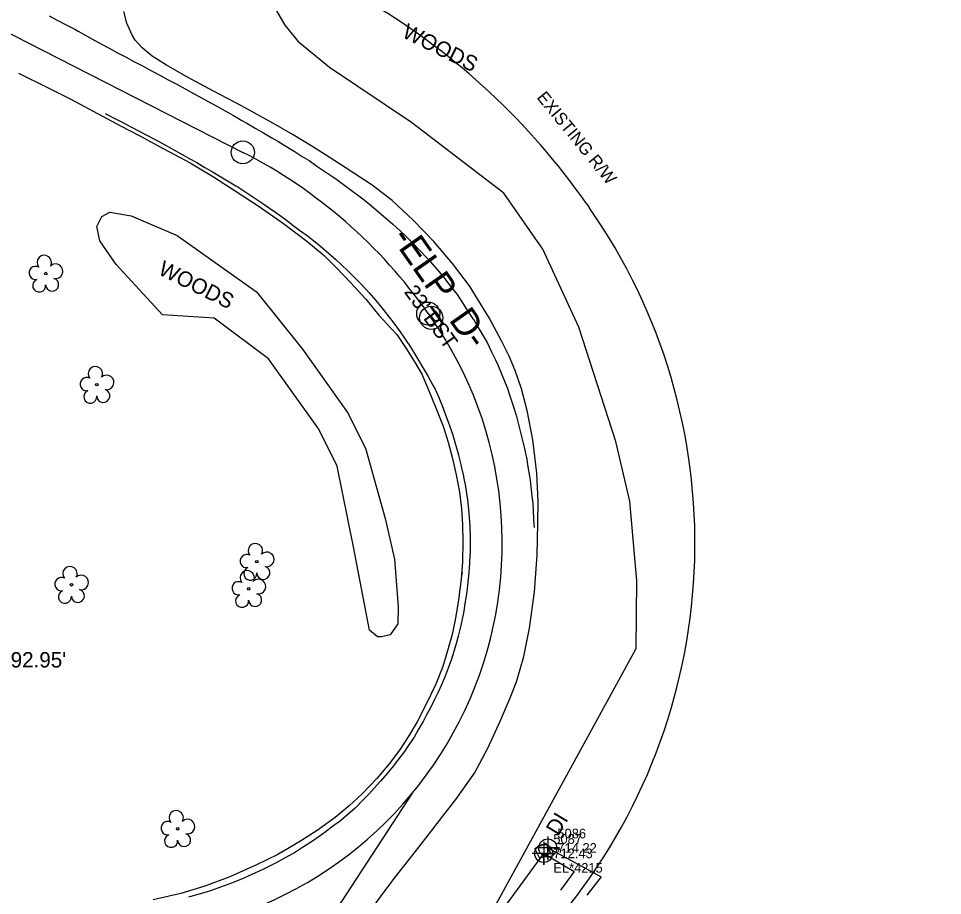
# Model space of a CAD drawing. Extents: x 1516784 to 1522736, y 634838 to 639369.
# Drawn here: x 1520674.9 to 1520914.7, y 637790.3 to 638018 of the extents above; entities that cross this region are included whole.
import ezdxf

# ---------------------------------------------------------------- set-up
doc = ezdxf.new("R2010")
doc.units = 0
for name, color, linetype in [('COGO Default Point Elevation', 7, 'Continuous'), ('COGO Default Point Number', 7, 'Continuous'), ('Exist Environmental Wetland Boundary Text', 7, 'Continuous'), ('Exist Horizontal Alignment Direction Label', 7, 'Continuous'), ('Exist Horizontal Alignment Point', 7, 'Continuous'), ('Exist Right of Way Line', 7, 'Continuous'), ('Exist Right of Way Line Text', 7, 'Continuous'), ('Exist Roads EOP Text', 7, 'Continuous'), ('Exist Structure Minor Drop Inlet', 7, 'Continuous'), ('Exist Structure Minor Drop Inlet Cogo Elevation', 7, 'Continuous'), ('Exist Structure Minor Drop Inlet Cogo Number', 7, 'Continuous'), ('Exist Structure Minor Drop Inlet Cogo Point CELL', 7, 'Continuous'), ('Exist Structure Minor Drop Inlet Leader', 7, 'Continuous'), ('Exist Structure Minor Drop Inlet Text', 7, 'Continuous'), ('Exist Structure Minor Pipes RCP 15 Inch', 7, 'Continuous'), ('Exist Structure Minor Pipes RCP 15 Inch Cogo Comment', 7, 'Continuous'), ('Exist Structure Minor Pipes RCP 15 Inch Cogo Elevation', 7, 'Continuous'), ('Exist Structure Minor Pipes RCP 15 Inch Cogo Number', 7, 'Continuous'), ('Exist Structure Minor Pipes RCP 15 Inch Cogo Point CELL', 7, 'Continuous'), ('Exist Structure Minor Pipes RCP 15 Inch Leader', 7, 'Continuous'), ('Exist Structure Minor Pipes RCP 66 Inch Invert', 7, 'Continuous'), ('Exist Vegetation Tree CELL', 7, 'Continuous'), ('Exist Vegetation Woods Line', 7, 'Continuous'), ('Exist Vegetation Woods Line Text', 7, 'Continuous'), ('Scratch_Level_5', 7, 'Continuous')]:
    doc.layers.add(name, color=color, linetype=linetype)

msp = doc.modelspace()

# ---------------------------------------------------------------- linework, layer by layer
at = {"layer": 'COGO Default Point Elevation'}
for points in [[(1520682.82, 638018.69), (1520685.04, 638017.54), (1520687.25, 638016.38), (1520689.46, 638015.22), (1520690.35, 638014.76), (1520692.53, 638013.54), (1520694.71, 638012.33), (1520696.89, 638011.11), (1520698.37, 638010.28), (1520700.58, 638009.12), (1520702.79, 638007.95), (1520705, 638006.78), (1520707.21, 638005.62), (1520709.42, 638004.45), (1520711.54, 638003.33), (1520713.73, 638002.14), (1520715.93, 638000.94), (1520718.12, 637999.75), (1520720.32, 637998.55), (1520722.51, 637997.36), (1520724.13, 637996.47), (1520726.31, 637995.25), (1520728.49, 637994.03), (1520730.66, 637992.8), (1520732.84, 637991.58), (1520734.16, 637990.84), (1520736.32, 637989.58), (1520738.48, 637988.32), (1520740.63, 637987.06), (1520742.13, 637986.19), (1520744.25, 637984.87), (1520746.37, 637983.55), (1520748.49, 637982.23), (1520750.26, 637981.13), (1520752.33, 637979.73), (1520754.4, 637978.33), (1520756.47, 637976.94), (1520757.17, 637976.46), (1520759.18, 637974.97), (1520761.18, 637973.48), (1520763.19, 637971.99), (1520764.54, 637970.98), (1520766.45, 637969.38), (1520768.37, 637967.78), (1520770.12, 637966.31), (1520771.97, 637964.63), (1520773.82, 637962.96), (1520775.56, 637961.38), (1520777.3, 637959.58), (1520779.03, 637957.78), (1520780.76, 637955.98), (1520781.17, 637955.56), (1520782.8, 637953.66), (1520784.43, 637951.77), (1520784.87, 637951.26), (1520786.39, 637949.28), (1520787.92, 637947.31), (1520788.67, 637946.33), (1520790.05, 637944.25), (1520791.43, 637942.17), (1520792.81, 637940.09), (1520792.91, 637939.94), (1520794.18, 637937.79), (1520795.45, 637935.64), (1520796.46, 637933.92), (1520797.55, 637931.67), (1520798.64, 637929.42), (1520799.29, 637928.1), (1520800.24, 637925.79), (1520801.2, 637923.48), (1520801.72, 637922.22), (1520802.48, 637919.84), (1520803.23, 637917.46), (1520803.99, 637915.06), (1520804.62, 637912.64), (1520805.25, 637910.22), (1520805.52, 637909.18), (1520806.07, 637906.74), (1520806.63, 637904.31), (1520806.67, 637904.11), (1520807.08, 637901.65), (1520807.49, 637899.19), (1520807.66, 637898.16), (1520807.94, 637895.68), (1520808.21, 637893.2), (1520808.23, 637892.97), (1520808.39, 637890.47), (1520808.54, 637887.98), (1520808.68, 637885.85)], [(1520697.33, 637993.37), (1520699.55, 637992.22), (1520701.77, 637991.07), (1520703.99, 637989.93), (1520706.21, 637988.78), (1520707.99, 637987.86), (1520710.19, 637986.67), (1520712.38, 637985.48), (1520714.58, 637984.29), (1520715.18, 637983.96), (1520717.36, 637982.74), (1520719.54, 637981.52), (1520721.11, 637980.64), (1520723.26, 637979.36), (1520725.41, 637978.09), (1520726.97, 637977.16), (1520729.12, 637975.88), (1520731.26, 637974.59), (1520731.76, 637974.29), (1520733.85, 637972.92), (1520735.94, 637971.55), (1520736.48, 637971.19), (1520738.55, 637969.79), (1520740.61, 637968.39), (1520741.08, 637968.07), (1520743.09, 637966.59), (1520745.11, 637965.11), (1520745.82, 637964.58), (1520747.83, 637963.1), (1520749.83, 637961.62), (1520750.32, 637961.26), (1520752.27, 637959.7), (1520752.69, 637959.37), (1520754.59, 637957.74), (1520755.31, 637957.12), (1520757.18, 637955.45), (1520758.58, 637954.2), (1520760.38, 637952.47), (1520761.19, 637951.69), (1520762.95, 637949.92), (1520763.49, 637949.38), (1520765.19, 637947.55), (1520765.91, 637946.78), (1520767.56, 637944.84), (1520769.16, 637942.93), (1520769.53, 637942.49), (1520771.05, 637940.52), (1520771.98, 637939.3), (1520773.45, 637937.28), (1520774.49, 637935.84), (1520775.91, 637933.78), (1520776.05, 637933.58), (1520777.38, 637931.47), (1520777.47, 637931.33), (1520778.76, 637929.19), (1520779.39, 637928.14), (1520780.67, 637925.99), (1520781.21, 637925.06), (1520782.4, 637922.86), (1520783, 637921.76), (1520784, 637919.47), (1520784.12, 637919.19), (1520785.05, 637916.87), (1520785.37, 637916.08), (1520786.24, 637913.73), (1520786.41, 637913.28), (1520787.22, 637910.92), (1520787.59, 637909.85), (1520788.3, 637907.46), (1520788.38, 637907.19), (1520789.03, 637904.78), (1520789.07, 637904.64), (1520789.65, 637902.21), (1520789.77, 637901.68), (1520790.31, 637899.24), (1520790.35, 637899.04), (1520790.83, 637896.54), (1520791.21, 637894.07), (1520791.35, 637893.13), (1520791.61, 637890.6), (1520791.81, 637888.59), (1520791.97, 637886.03), (1520792.05, 637883.53), (1520792.06, 637883.12), (1520792.05, 637880.62), (1520792.04, 637879.58), (1520791.92, 637877.09), (1520791.9, 637876.65), (1520791.7, 637874.16), (1520791.58, 637872.56), (1520791.29, 637870.08), (1520791.12, 637868.6), (1520790.72, 637866.14), (1520790.4, 637864.14), (1520789.89, 637861.69), (1520789.56, 637860.09), (1520788.97, 637857.67), (1520788.57, 637856.07), (1520787.83, 637853.69), (1520787.2, 637851.69), (1520786.34, 637849.34), (1520785.6, 637847.31), (1520784.62, 637845.02), (1520783.88, 637843.28), (1520782.78, 637841.04), (1520781.9, 637839.26), (1520780.7, 637837.07), (1520779.84, 637835.51), (1520778.61, 637833.33), (1520777.55, 637831.48), (1520776.13, 637829.42), (1520775, 637827.77), (1520773.5, 637825.77), (1520772.14, 637823.95), (1520770.52, 637822.04), (1520768.85, 637820.07), (1520767.17, 637818.21), (1520765.86, 637816.76), (1520764.11, 637814.97), (1520762.37, 637813.18), (1520762.2, 637813.01), (1520760.31, 637811.38), (1520758.39, 637809.72), (1520756.39, 637808.23), (1520754.39, 637806.73), (1520754.11, 637806.52), (1520752.05, 637805.1), (1520750.67, 637804.15), (1520748.57, 637802.81), (1520746.46, 637801.46), (1520746.12, 637801.24), (1520743.92, 637800.05), (1520741.73, 637798.86), (1520740.66, 637798.29), (1520738.41, 637797.2), (1520736.16, 637796.12), (1520735.61, 637795.85), (1520733.31, 637794.86), (1520731.02, 637793.87), (1520730.8, 637793.78), (1520728.46, 637792.92), (1520727.05, 637792.4), (1520724.69, 637791.6), (1520723.61, 637791.23), (1520721.43, 637790.57), (1520719.02, 637789.88)]]:
    msp.add_lwpolyline(points, dxfattribs=at)
at = {"layer": 'COGO Default Point Number'}
msp.add_line((1520789.86, 637872.85), (1520790.06, 637874.32), dxfattribs=at)
for points in [[(1520766.29, 637786.51), (1520769.49, 637790.94), (1520772.99, 637795.51), (1520776.91, 637800.55), (1520781.16, 637805.97), (1520785.03, 637810.93), (1520788.36, 637815.28), (1520793.2, 637822.11), (1520796.67, 637828.59), (1520799.93, 637835.82), (1520802.32, 637841.26), (1520804.08, 637845.85), (1520806.02, 637852.4), (1520807.51, 637859.75), (1520808.77, 637869.15), (1520809.43, 637878.68), (1520809.66, 637886.95), (1520809.69, 637892.73), (1520809.36, 637899.99), (1520808.33, 637908.65), (1520806.83, 637916.28), (1520805.4, 637921.85), (1520803.78, 637926.63), (1520802.23, 637930.37), (1520800.2, 637934.33), (1520797, 637940.3), (1520791.92, 637948.61), (1520787.52, 637954.45), (1520782.68, 637960.11), (1520777.32, 637965.71), (1520771.84, 637970.78), (1520766.65, 637974.74), (1520759.64, 637979.37), (1520755.47, 637982.04), (1520751, 637984.84), (1520746.13, 637987.79), (1520741, 637990.79), (1520732.71, 637995.33), (1520725.43, 637999.16), (1520718.52, 638002.87), (1520713.3, 638005.89), (1520709.59, 638008.25), (1520706.99, 638010.38), (1520705.12, 638012.42), (1520704.33, 638013.7), (1520703.01, 638016.82), (1520702.16, 638019.83)], [(1520674.85, 638003.8), (1520682.22, 638000.21), (1520688.24, 637997.19), (1520696.68, 637992.66), (1520701.36, 637990.18), (1520706.32, 637987.57), (1520711.14, 637985.01), (1520719.41, 637980.53), (1520725.47, 637976.93), (1520731.07, 637973.32), (1520737.32, 637969.25), (1520743.63, 637964.83), (1520749.71, 637960.24), (1520754.15, 637956.53), (1520757.34, 637953.35), (1520761.12, 637949.43), (1520764.97, 637945.16), (1520768.4, 637941.04), (1520771.59, 637937.55), (1520773.03, 637936.01), (1520775.47, 637932.36), (1520777.77, 637928.66), (1520779.54, 637925.65), (1520781.27, 637921.59), (1520783.16, 637916.93), (1520785.08, 637912.16), (1520786.34, 637908.06), (1520787.52, 637903.84), (1520788.46, 637899.55), (1520789.3, 637895.04), (1520789.86, 637890.73), (1520790.12, 637886.62), (1520790.19, 637882.31), (1520790.12, 637876.96), (1520789.77, 637872.51), (1520789.06, 637867.14), (1520788.28, 637862.31), (1520787.39, 637858.09), (1520786.39, 637854.45), (1520784.97, 637849.83), (1520783.15, 637845.22), (1520780.58, 637839.85), (1520778.29, 637835.46), (1520776.2, 637831.78), (1520773.78, 637828.11), (1520771.04, 637824.53), (1520767.84, 637820.7), (1520764.09, 637816.75), (1520760.67, 637813.6), (1520757.03, 637810.64), (1520752.37, 637807.25), (1520747.61, 637804.22), (1520742.21, 637801.02), (1520736.47, 637798.18), (1520729.68, 637795.19), (1520723.24, 637792.74), (1520716.96, 637790.83), (1520709.81, 637789.2)]]:
    msp.add_lwpolyline(points, dxfattribs=at)
at = {"layer": 'Exist Environmental Wetland Boundary Text'}
for p, q in [((1520558.04, 638072.63), (1520733.08, 637983.28)), ((1520781.21, 637941.41), (1520781.97, 637940.32)), ((1520777.06, 637816.88), (1520734.69, 637752.1))]:
    msp.add_line(p, q, dxfattribs=at)
for centre, radius, start, end in [((1520673.07, 637865.71), 132, 34.9928, 62.9577), ((1520698.41, 637881.83), 102, 278.3238, 34.9928), ((1520686.59, 637943.77), 165, 244.2197, 278.3238)]:
    msp.add_arc(centre, radius, start, end, dxfattribs=at)
at = {"layer": 'Exist Horizontal Alignment Point'}
for centre in [(1520733.08, 637983.28), (1520781.21, 637941.41), (1520781.97, 637940.32)]:
    msp.add_circle(centre, 3, dxfattribs=at)
at = {"layer": 'Exist Right of Way Line'}
msp.add_line((1520822.17, 637970.08), (1520822.93, 637968.99), dxfattribs=at)
for centre, radius, start, end in [((1520673.07, 637865.71), 182, 34.9928, 59.0667), ((1520698.41, 637881.83), 152, 321.6004, 34.9928)]:
    msp.add_arc(centre, radius, start, end, dxfattribs=at)
at = {"layer": 'Exist Structure Minor Drop Inlet'}
msp.add_lwpolyline([(1520808.88, 637802.58), (1520811.71, 637803.94), (1520812.97, 637801.34), (1520810.13, 637799.98)], close=True, dxfattribs=at)
at = {"layer": 'Exist Structure Minor Drop Inlet Cogo Point CELL'}
msp.add_lwpolyline([(1520812.22, 637805.69), (1520812.22, 637799.69), (1520812.22, 637802.69), (1520815.22, 637802.69), (1520809.22, 637802.69)], dxfattribs=at)
msp.add_circle((1520812.22, 637802.69), 2.34, dxfattribs=at)
at = {"layer": 'Exist Structure Minor Drop Inlet Leader'}
msp.add_lwpolyline([(1520812.22, 637802.69), (1520826.04, 637795.2), (1520822.37, 637790.46)], dxfattribs=at)
at = {"layer": 'Exist Structure Minor Pipes RCP 15 Inch'}
msp.add_line((1520750.03, 637717.71), (1520811.16, 637801.28), dxfattribs=at)
at = {"layer": 'Exist Structure Minor Pipes RCP 15 Inch Cogo Point CELL'}
msp.add_lwpolyline([(1520811.16, 637804.28), (1520811.16, 637798.28), (1520811.16, 637801.28), (1520814.16, 637801.28), (1520808.16, 637801.28)], dxfattribs=at)
msp.add_circle((1520811.16, 637801.28), 2.34, dxfattribs=at)
at = {"layer": 'Exist Structure Minor Pipes RCP 15 Inch Leader'}
msp.add_lwpolyline([(1520811.16, 637801.28), (1520819.07, 637796.59), (1520815.5, 637791.76)], dxfattribs=at)
at = {"layer": 'Exist Vegetation Tree CELL'}
for p, q in [((1520681.94, 637951.81), (1520681.94, 637951.81)), ((1520695.19, 637922.96), (1520695.19, 637922.96)), ((1520736.73, 637877.01), (1520736.73, 637877.01)), ((1520688.61, 637871.02), (1520688.61, 637871.02)), ((1520734.61, 637869.96), (1520734.61, 637869.96)), ((1520716.18, 637807.65), (1520716.18, 637807.65))]:
    msp.add_line(p, q, dxfattribs=at)
for centre in [(1520681.94, 637951.81), (1520695.19, 637922.96), (1520736.73, 637877.01), (1520688.61, 637871.02), (1520734.61, 637869.96), (1520716.18, 637807.65)]:
    msp.add_circle(centre, 0.326, dxfattribs=at)
for centre, radius, start, end in [((1520681.55, 637954.69), 1.86, 330.1651, 219.7134), ((1520684.49, 637952.4), 1.9, 257.1011, 134.1999), ((1520679.33, 637951.97), 1.73, 62.6636, 279.3457), ((1520680.23, 637948.69), 1.69, 111.5671, 6.231), ((1520683.61, 637948.91), 1.7, 181.2822, 74.56), ((1520694.81, 637925.83), 1.86, 330.1651, 219.7134), ((1520697.74, 637923.55), 1.9, 257.1011, 134.1999), ((1520692.59, 637923.11), 1.73, 62.6636, 279.3457), ((1520693.49, 637919.84), 1.69, 111.5671, 6.231), ((1520696.87, 637920.06), 1.7, 181.2822, 74.56), ((1520736.34, 637879.89), 1.86, 330.1651, 219.7134), ((1520739.28, 637877.6), 1.9, 257.1011, 134.1999), ((1520734.12, 637877.17), 1.73, 62.6636, 279.3457), ((1520688.22, 637873.9), 1.86, 330.1651, 219.7134), ((1520734.22, 637872.83), 1.86, 330.1651, 219.7134), ((1520735.03, 637873.89), 1.69, 111.5671, 6.231), ((1520738.4, 637874.12), 1.7, 181.2822, 74.56), ((1520686, 637871.18), 1.73, 62.6636, 279.3457), ((1520691.16, 637871.61), 1.9, 257.1011, 134.1999), ((1520737.15, 637870.55), 1.9, 257.1011, 134.1999), ((1520732, 637870.11), 1.73, 62.6636, 279.3457), ((1520686.9, 637867.9), 1.69, 111.5671, 6.231), ((1520690.28, 637868.12), 1.7, 181.2822, 74.56), ((1520732.9, 637866.84), 1.69, 111.5671, 6.231), ((1520736.28, 637867.06), 1.7, 181.2822, 74.56), ((1520715.79, 637810.53), 1.86, 330.1651, 219.7134), ((1520718.73, 637808.24), 1.9, 257.1011, 134.1999), ((1520713.57, 637807.81), 1.73, 62.6636, 279.3457), ((1520714.47, 637804.53), 1.69, 111.5671, 6.231), ((1520717.85, 637804.75), 1.7, 181.2822, 74.56)]:
    msp.add_arc(centre, radius, start, end, dxfattribs=at)
at = {"layer": 'Exist Vegetation Woods Line'}
for points in [[(1520835.15, 637854.49), (1520835.3, 637872.01), (1520833.5, 637892.76), (1520829.84, 637908.22), (1520820.24, 637937.86), (1520810.92, 637958.11), (1520800.8, 637972.65), (1520776.89, 637991.05), (1520755.55, 638005.29), (1520747.84, 638011.64), (1520744.03, 638016.3), (1520740.73, 638022.06)], [(1520765.97, 637859.24), (1520761.77, 637880.83), (1520757.55, 637901.79), (1520752.77, 637911.45), (1520739.72, 637929.7), (1520725.66, 637940.21), (1520712.26, 637941.07), (1520700.22, 637954.14), (1520695.94, 637960.33), (1520695.23, 637964.03), (1520696.48, 637966.6), (1520698.54, 637967.71), (1520704.12, 637966.8), (1520716.04, 637961.66), (1520736.59, 637947.03), (1520748.53, 637932.2), (1520760.23, 637915.78), (1520764.91, 637906.48), (1520770.02, 637888.22), (1520772.41, 637877.67), (1520773.39, 637865.31), (1520773.3, 637860.89), (1520771.36, 637858.03), (1520769.05, 637857.51), (1520768.01, 637857.48), (1520765.97, 637859.24)], [(1520763.42, 637701.14), (1520763.38, 637708.21), (1520763.5, 637714.78), (1520764.37, 637721.48), (1520766.84, 637728.8), (1520769.88, 637734.98), (1520773.01, 637741.3), (1520783.78, 637760.55), (1520835.15, 637854.49)]]:
    msp.add_lwpolyline(points, dxfattribs=at)

# ---------------------------------------------------------------- texts
at = {"layer": 'Exist Horizontal Alignment Direction Label'}
msp.add_text('-ELP_D-', height=7, rotation=304.9928, dxfattribs=at).set_placement((1520771.47, 637961.11))
at = {"layer": 'Exist Right of Way Line Text'}
msp.add_text('EXISTING R/W', height=3.2, rotation=309.2237, dxfattribs=at).set_placement((1520809.2, 637997.47))
at = {"layer": 'Exist Roads EOP Text'}
msp.add_text("23' BST", height=4, rotation=306.1084, dxfattribs=at).set_placement((1520774.78, 637947.03))
at = {"layer": 'Exist Structure Minor Drop Inlet Cogo Elevation'}
msp.add_text('714.22', height=2.5, dxfattribs=at).set_placement((1520814.72, 637801.44))
at = {"layer": 'Exist Structure Minor Drop Inlet Cogo Number'}
msp.add_text('5086', height=2.5, dxfattribs=at).set_placement((1520814.72, 637805.19))
at = {"layer": 'Exist Structure Minor Drop Inlet Text'}
msp.add_text('DI', height=4, rotation=59.1327, dxfattribs=at).set_placement((1520814.95, 637805.66))
at = {"layer": 'Exist Structure Minor Pipes RCP 15 Inch Cogo Comment'}
msp.add_text('EL*4215', height=2.5, dxfattribs=at).set_placement((1520813.66, 637796.28))
at = {"layer": 'Exist Structure Minor Pipes RCP 15 Inch Cogo Elevation'}
msp.add_text('712.43', height=2.5, dxfattribs=at).set_placement((1520813.66, 637800.03))
at = {"layer": 'Exist Structure Minor Pipes RCP 15 Inch Cogo Number'}
msp.add_text('5087', height=2.5, dxfattribs=at).set_placement((1520813.66, 637803.78))
at = {"layer": 'Exist Structure Minor Pipes RCP 66 Inch Invert'}
msp.add_text("INV=692.95'", height=4, dxfattribs=at).set_placement((1520657.82, 637849.54))
at = {"layer": 'Exist Vegetation Woods Line Text'}
for p in [(1520774.15, 638013.3), (1520710.85, 637951.76)]:
    msp.add_text('WOODS', height=4, rotation=333.5021, dxfattribs=at).set_placement(p)
at = {"layer": 'Scratch_Level_5'}
msp.add_text('COLUMN LOCATION', height=500, rotation=335.0373, dxfattribs=at).set_placement((1516680.97, 637558.94))

doc.saveas('drawing.dxf')
